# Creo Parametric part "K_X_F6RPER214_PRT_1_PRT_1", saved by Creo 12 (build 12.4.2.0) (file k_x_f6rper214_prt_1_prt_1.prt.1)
Units: Custom; MM, KILOGRAM, SECS

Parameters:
  PTC_WM_ITERATION = "0"
  PTC_WM_VERSION = "-.0"
  PTC_WM_LIFECYCLE_STATE = "In Work"
  PTC_WM_LIFECYCLE = "MO_CADDocument"
  PTC_WM_CREATED_BY = "Maximilian Roepper (Z0017RMS: MO)"
  PTC_WM_CREATED_ON = "18-Sep-26 11:36:42 AM"
  PTC_WM_MODIFIED_BY = "Maximilian Roepper (Z0017RMS: MO)"
  PTC_WM_MODIFIED_ON = "18-Sep-26 11:36:46 AM"
  PDMLINKNUMBER = "PDM000071455338"
  PTC_WM_NAME = "k_x_f6rper214_prt_1_prt_1.prt"
  PTC_WM_NUMBER = "PDM000071455338"

Other parameters: WEIGHT, WEIGHT_FACTOR, WEIGHT_ADD, _MASS_TEMP, _DIFF_TEMP, MC_ERRORS, SUPPLIER

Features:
  1. coordinate system
  2. datum plane "PRT_YZ"
  3. datum plane "PRT_XY"
  4. datum plane "PRT_XZ"
  5. coordinate system
  6. datum axis
  7. datum axis
  8. datum axis
  9. coordinate system
  10. imported feature
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
Other named items: PRT, SIEMENS_MO, DRW_VIEW_ORG, PRT_X, PRT_Y, PRT_Z, CS0, ROUGH_GROB

Layers: 00_STD_CSYS-KSYS, 01_STD_PLANES-EBENEN, 02_STD_AXES-ACHSEN, 03_STD_CSYS-KSYS, 24_IMPORT_FEAT-IMPORT_KE

Surfaces: 28 tabulated cylinder, 4 plane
